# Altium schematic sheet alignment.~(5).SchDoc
size A4
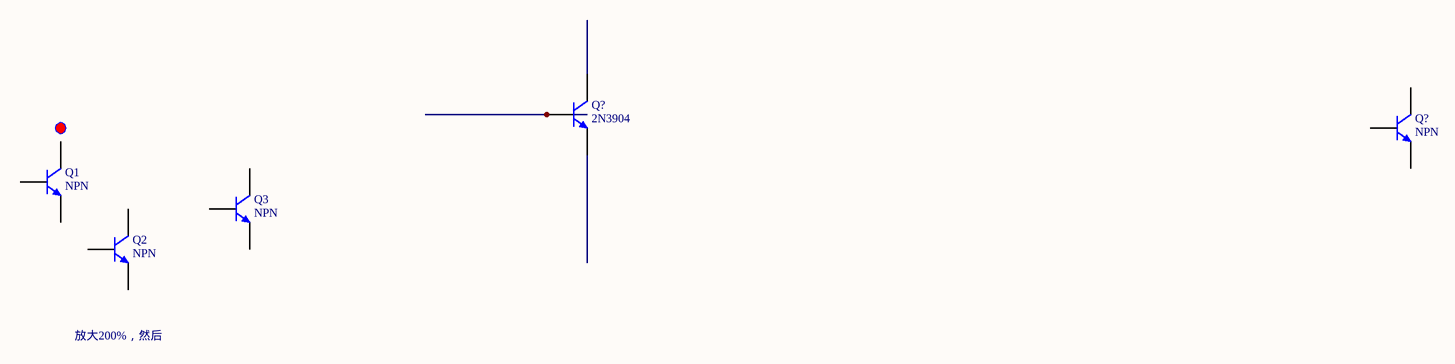
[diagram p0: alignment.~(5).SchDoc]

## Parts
(Parts that share a designator on the sheet are numbered #1, #2 ... from top to bottom, then left to right.)
Q1  NPN  [BCY-W3]
Q2  NPN  [BCY-W3]
Q3  NPN  [BCY-W3]
Q?#1  2N3904  [BCY-W3/E4]
Q?#2  NPN  [BCY-W3]

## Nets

Not connected (* = marked no-connect by the designer): Q1 1(C) 2(B) 3(E); Q2 1(C) 2(B) 3(E); Q3 1(C) 2(B) 3(E); Q?#1 1(E) 2(B) 3(C); Q?#2 1(C) 2(B) 3(E)

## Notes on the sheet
- 放大200%，然后

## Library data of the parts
Q1-Q3 Q?#2 = NPN: NPN Bipolar Transistor
Q?#1 = 2N3904: NPN General Purpose Amplifier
